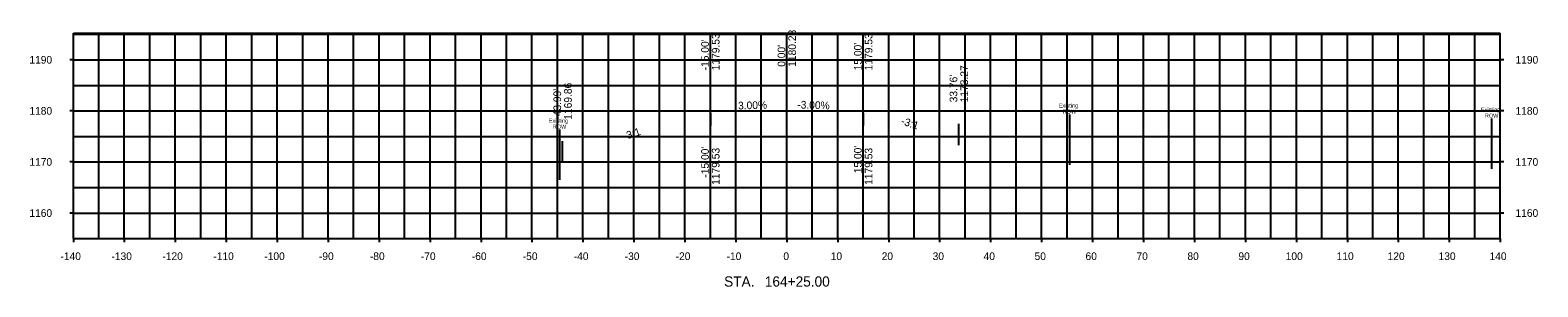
# Model space of a CAD drawing. Extents: x -148 to 147, y 1146 to 1196.
import ezdxf

# ---------------------------------------------------------------- set-up
doc = ezdxf.new("R2010")
doc.units = 0
for name, color, linetype in [('_CIVIL_CONSTRUCTION', 7, 'Continuous'), ('Default', 7, 'Continuous'), ('DisROW Existing', 7, 'Continuous'), ('Roadways', 7, 'Continuous'), ('ROWLines', 7, 'Continuous'), ('Topography', 7, 'Continuous')]:
    doc.layers.add(name, color=color, linetype=linetype)

msp = doc.modelspace()

# ---------------------------------------------------------------- linework, layer by layer
at = {"layer": '_CIVIL_CONSTRUCTION'}
for p, q in [((-15, 1179.53), (-15, 1183.73)), ((0, 1180.23), (0, 1184.43)), ((15, 1179.53), (15, 1183.73)), ((15, 1179.53), (15, 1183.73)), ((-15, 1179.53), (-15, 1177.13)), ((15, 1179.53), (15, 1177.13)), ((33.76, 1173.27), (33.76, 1177.47)), ((-43.99, 1169.86), (-43.99, 1174.06))]:
    msp.add_line(p, q, dxfattribs=at)
at = {"layer": 'DisROW Existing'}
for p, q in [((-130, 1155), (-130, 1195.23)), ((-120, 1155), (-120, 1195.23)), ((-110, 1155), (-110, 1195.23)), ((-100, 1155), (-100, 1195.23)), ((-90, 1155), (-90, 1195.23)), ((-80, 1155), (-80, 1195.23)), ((-70, 1155), (-70, 1195.23)), ((-60, 1155), (-60, 1195.23)), ((-50, 1155), (-50, 1195.23)), ((-40, 1155), (-40, 1195.23)), ((-30, 1155), (-30, 1195.23)), ((-20, 1155), (-20, 1195.23)), ((-10, 1155), (-10, 1195.23)), ((0, 1155), (0, 1195.23)), ((10, 1155), (10, 1195.23)), ((20, 1155), (20, 1195.23)), ((30, 1155), (30, 1195.23)), ((40, 1155), (40, 1195.23)), ((50, 1155), (50, 1195.23)), ((60, 1155), (60, 1195.23)), ((70, 1155), (70, 1195.23)), ((80, 1155), (80, 1195.23)), ((90, 1155), (90, 1195.23)), ((100, 1155), (100, 1195.23)), ((110, 1155), (110, 1195.23)), ((120, 1155), (120, 1195.23)), ((130, 1155), (130, 1195.23)), ((-140, 1190), (-140.72, 1190)), ((-140, 1190), (140, 1190)), ((140.72, 1190), (140, 1190)), ((-140, 1180), (-140.72, 1180)), ((-140, 1180), (140, 1180)), ((140.72, 1180), (140, 1180)), ((-140, 1170), (-140.72, 1170)), ((-140, 1170), (140, 1170)), ((140.72, 1170), (140, 1170)), ((-140, 1160), (-140.72, 1160)), ((-140, 1160), (140, 1160)), ((140.72, 1160), (140, 1160)), ((-140, 1155), (-140, 1154.28)), ((-130, 1155), (-130, 1154.28)), ((-120, 1155), (-120, 1154.28)), ((-110, 1155), (-110, 1154.28)), ((-100, 1155), (-100, 1154.28)), ((-90, 1155), (-90, 1154.28)), ((-80, 1155), (-80, 1154.28)), ((-70, 1155), (-70, 1154.28)), ((-60, 1155), (-60, 1154.28)), ((-50, 1155), (-50, 1154.28)), ((-40, 1155), (-40, 1154.28)), ((-30, 1155), (-30, 1154.28)), ((-20, 1155), (-20, 1154.28)), ((-10, 1155), (-10, 1154.28)), ((0, 1155), (0, 1154.28)), ((10, 1155), (10, 1154.28)), ((20, 1155), (20, 1154.28)), ((30, 1155), (30, 1154.28)), ((40, 1155), (40, 1154.28)), ((50, 1155), (50, 1154.28)), ((60, 1155), (60, 1154.28)), ((70, 1155), (70, 1154.28)), ((80, 1155), (80, 1154.28)), ((90, 1155), (90, 1154.28)), ((100, 1155), (100, 1154.28)), ((110, 1155), (110, 1154.28)), ((120, 1155), (120, 1154.28)), ((130, 1155), (130, 1154.28)), ((140, 1155), (140, 1154.28))]:
    msp.add_line(p, q, dxfattribs=at)
at = {"layer": 'Roadways'}
for p, q in [((-140, 1195), (140, 1195)), ((-135, 1155), (-135, 1195.23)), ((-125, 1155), (-125, 1195.23)), ((-115, 1155), (-115, 1195.23)), ((-105, 1155), (-105, 1195.23)), ((-95, 1155), (-95, 1195.23)), ((-85, 1155), (-85, 1195.23)), ((-75, 1155), (-75, 1195.23)), ((-65, 1155), (-65, 1195.23)), ((-55, 1155), (-55, 1195.23)), ((-45, 1155), (-45, 1195.23)), ((-35, 1155), (-35, 1195.23)), ((-25, 1155), (-25, 1195.23)), ((-15, 1155), (-15, 1195.23)), ((-5, 1155), (-5, 1195.23)), ((5, 1155), (5, 1195.23)), ((15, 1155), (15, 1195.23)), ((25, 1155), (25, 1195.23)), ((35, 1155), (35, 1195.23)), ((45, 1155), (45, 1195.23)), ((55, 1155), (55, 1195.23)), ((65, 1155), (65, 1195.23)), ((75, 1155), (75, 1195.23)), ((85, 1155), (85, 1195.23)), ((95, 1155), (95, 1195.23)), ((105, 1155), (105, 1195.23)), ((115, 1155), (115, 1195.23)), ((125, 1155), (125, 1195.23)), ((135, 1155), (135, 1195.23)), ((-140, 1185), (140, 1185)), ((-140, 1175), (140, 1175)), ((-140, 1165), (140, 1165))]:
    msp.add_line(p, q, dxfattribs=at)
at = {"layer": 'ROWLines'}
for p, q in [((-140, 1195.23), (140, 1195.23)), ((-140, 1155), (-140, 1195.23)), ((140, 1155), (140, 1195.23)), ((-140, 1155), (140, 1155))]:
    msp.add_line(p, q, dxfattribs=at)
at = {"layer": 'Topography'}
for p, q in [((55.46, 1179.3), (55.46, 1169.46)), ((138.3, 1178.5), (138.3, 1168.66)), ((-44.61, 1176.34), (-44.61, 1166.49))]:
    msp.add_line(p, q, dxfattribs=at)

# ---------------------------------------------------------------- texts
at = {"layer": '_CIVIL_CONSTRUCTION'}
for s, rotation, p in [('1180.23', 90, (1.8, 1188.63)), ("-15.00'", 90, (-15.3, 1187.93)), ('1179.53', 90, (-13.2, 1187.93)), ("0.00'", 90, (-0.3, 1188.63)), ("15.00'", 90, (14.7, 1187.93)), ("15.00'", 90, (14.7, 1187.93)), ('1179.53', 90, (16.8, 1187.93)), ('1179.53', 90, (16.8, 1187.93)), ("33.76'", 90, (33.46, 1181.67)), ('1173.27', 90, (35.56, 1181.67)), ("-43.99'", 90, (-44.29, 1178.26)), ('1169.86', 90, (-42.19, 1178.26)), ('3.00%', 1.7184, (-9.54, 1180.27)), ('-3.00%', 358.2816, (2.04, 1180.49)), ('-3:1', 341.5668, (22.3, 1177.42)), ('3:1', 18.4332, (-31.19, 1174.46)), ("-15.00'", 90, (-15.3, 1166.93)), ('1179.53', 90, (-13.2, 1165.51)), ("15.00'", 90, (14.7, 1167.78)), ('1179.53', 90, (16.8, 1165.51))]:
    msp.add_text(s, height=1.5, rotation=rotation, dxfattribs=at).set_placement(p)
at = {"layer": 'Default'}
for s, height, p in [('1190', 1.5, (-148.63, 1189.25)), ('1190', 1.5, (143, 1189.25)), ('1180', 1.5, (-148.63, 1179.25)), ('1180', 1.5, (143, 1179.25)), ('1170', 1.5, (-148.63, 1169.25)), ('1170', 1.5, (143, 1169.25)), ('1160', 1.5, (-148.63, 1159.25)), ('1160', 1.5, (143, 1159.25)), ('-140', 1.5, (-142.53, 1150.8)), ('-130', 1.5, (-132.53, 1150.8)), ('-120', 1.5, (-122.53, 1150.8)), ('-110', 1.5, (-112.53, 1150.8)), ('-100', 1.5, (-102.53, 1150.8)), ('-90', 1.5, (-91.81, 1150.8)), ('-80', 1.5, (-81.81, 1150.8)), ('-70', 1.5, (-71.81, 1150.8)), ('-60', 1.5, (-61.81, 1150.8)), ('-50', 1.5, (-51.81, 1150.8)), ('-40', 1.5, (-41.81, 1150.8)), ('-30', 1.5, (-31.81, 1150.8)), ('-20', 1.5, (-21.81, 1150.8)), ('-10', 1.5, (-11.81, 1150.8)), ('0', 1.5, (-0.67, 1150.8)), ('10', 1.5, (8.62, 1150.8)), ('20', 1.5, (18.62, 1150.8)), ('30', 1.5, (28.62, 1150.8)), ('40', 1.5, (38.62, 1150.8)), ('50', 1.5, (48.62, 1150.8)), ('60', 1.5, (58.62, 1150.8)), ('70', 1.5, (68.62, 1150.8)), ('80', 1.5, (78.62, 1150.8)), ('90', 1.5, (88.62, 1150.8)), ('100', 1.5, (97.9, 1150.8)), ('110', 1.5, (107.9, 1150.8)), ('120', 1.5, (117.9, 1150.8)), ('130', 1.5, (127.9, 1150.8)), ('140', 1.5, (137.9, 1150.8)), ('STA.', 2.004, (-12.3, 1145.6)), ('164+25.00', 2.004, (-4.31, 1145.6))]:
    msp.add_text(s, height=height, dxfattribs=at).set_placement(p)
at = {"layer": 'Topography'}
for s, p in [('Existing', (53.37, 1180.65)), ('Existing', (136.21, 1179.86)), ('Existing', (-46.7, 1177.69)), ('ROW', (54.14, 1179.47)), ('ROW', (136.98, 1178.67)), ('ROW', (-45.93, 1176.51))]:
    msp.add_text(s, height=0.787, dxfattribs=at).set_placement(p)

doc.saveas('drawing.dxf')
